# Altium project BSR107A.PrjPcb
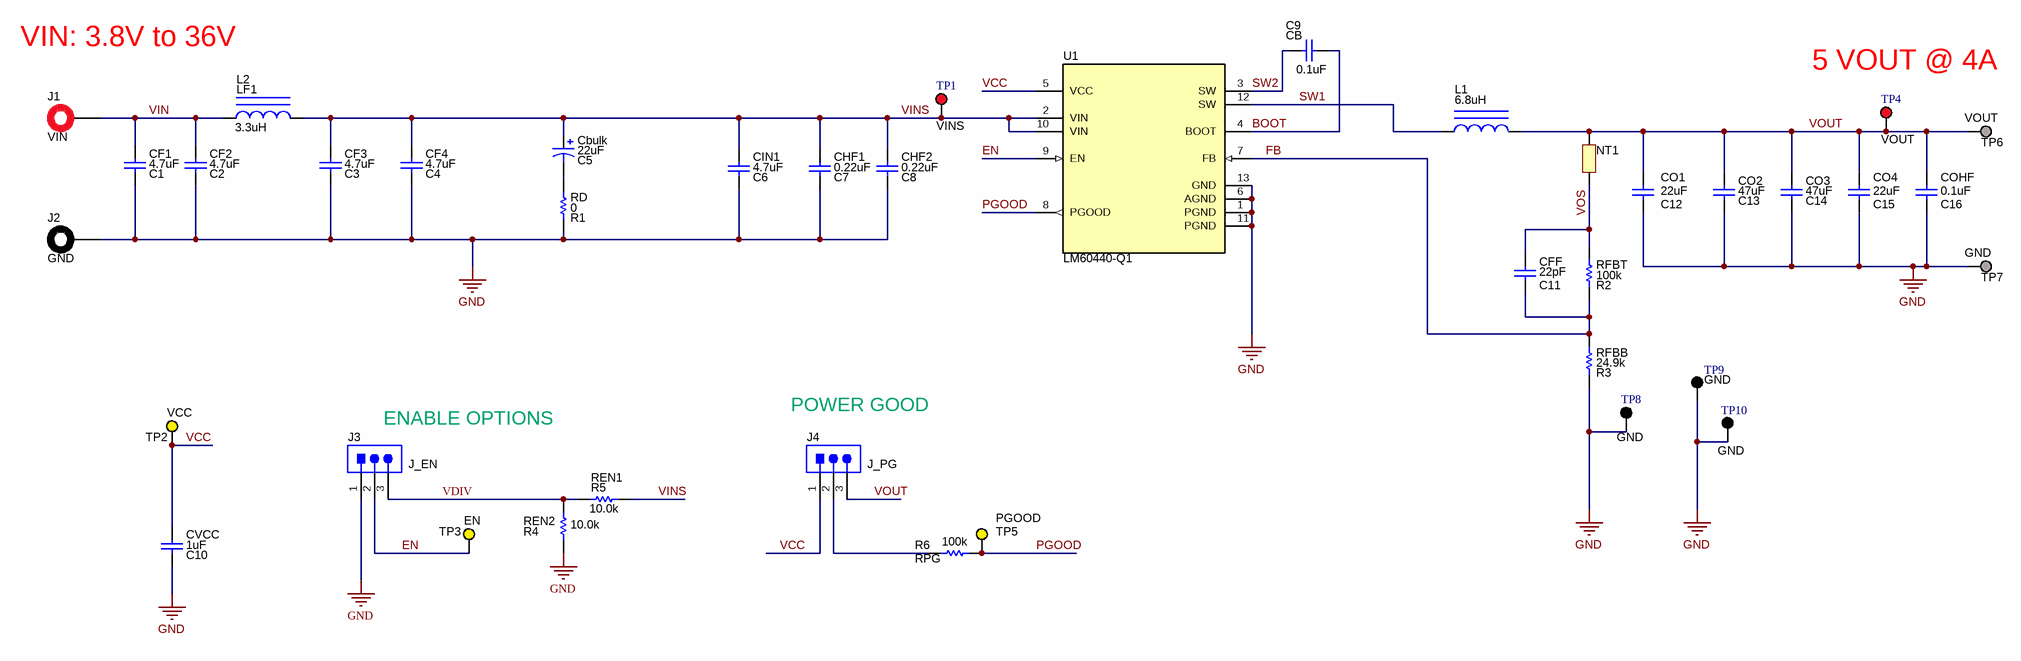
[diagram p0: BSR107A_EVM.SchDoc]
CopyrightYear: 2019; EVM_orderable: LM60440AQEVM; PCB_Layout: Ethan; PCB_Rev: A; PRJ_Customer: Public Release; PRJ_Engineer: Ethan Than; PRJ_Number: BSR107; PRJ_Title: LM60440AQEVM; SCH_Rev: A; TechSupport: http://www.ti.com/support; TID: N/A
2 sheets, 59 parts. Net scope: global (net labels, ports and power ports of the same name join across sheets).
Board file: BSR107A_PCB.PcbDoc
Sheets:
  BSR107A_EVM.SchDoc
  BSR107A_EVM_Hardware.SchDoc

## Sheet BSR107A_EVM.SchDoc
size 431 x 279 mm; Date: Not shown in title block; ApprovedBy: Not shown in title block; CheckedBy: Not shown in title block; Author: Not shown in title block; CompanyName: Not shown in title block; Engineer: Not shown in title block; Organization: Not shown in title block; Address1: Not shown in title block; Address2: Not shown in title block; Address3: Not shown in title block; Address4: Not shown in title block; DocumentNumber: 1; Revision: Use project parameter SCH_Rev; SheetNumber: 1; SheetTotal: 2; PageSetup: Record=PageOptions¦CenterHorizontal=True¦CenterVertical=True¦PrintScale=1.00¦XCorrection=1.00¦YCorrection=1.00¦PrintKind=0¦BorderSize=5000000¦LeftOffset=0¦BottomOffset=0¦Orientation=2¦PaperLength=1000¦PaperWidth=1000¦Scale=100¦PaperSource=15¦PrintQuality=600¦MediaType=1¦DitherType=10¦PaperKind=Letter¦PrintScaleMode=1

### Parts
C1  CF1  ValueDisplayed: 4.7uF  [1206_180]
C2  CF2  ValueDisplayed: 4.7uF  [1206_180]
C3  CF3  ValueDisplayed: 4.7uF  [1206_180]
C4  CF4  ValueDisplayed: 4.7uF  [1206_180]
C5  Cbulk  ValueDisplayed: 22uF  [SM_RADIAL_D]
C6  CIN1  ValueDisplayed: 4.7uF  [0805L]
C7  CHF1  ValueDisplayed: 0.22uF  [0603L]
C8  CHF2  ValueDisplayed: 0.22uF  [0603L]
C9  CB  ValueDisplayed: 0.1uF  [0603L]
C10  CVCC  ValueDisplayed: 1uF  [0603L]
C11  CFF  ValueDisplayed: 22pF  [0603L]
C12  CO1  ValueDisplayed: 22uF  [1210L]
C13  CO2  ValueDisplayed: 47uF  [1210_270L]
C14  CO3  ValueDisplayed: 47uF  [1210_270L]
C15  CO4  ValueDisplayed: 22uF  [1210L]
C16  COHF  ValueDisplayed: 0.1uF  [0603L]
J1  VIN  [6091]
J2  GND  [6092]
J3  J_EN  [Samtec_HTSW-103-07-G-S]
J4  J_PG  [Samtec_HTSW-103-07-G-S]
L1  ValueDisplayed: 6.8uH  [XAL6060]  (hidden comment: XAL6060-682MEB)
L2  LF1  ValueDisplayed: 3.3uH  [XAL4030]
NT1  Net-Tie  [Net-Tie_10mil]  (value not drawn)  (net tie, no BOM)
R1  RD  ValueDisplayed: 0  [0603]
R2  RFBT  ValueDisplayed: 100k  [0603L]
R3  RFBB  ValueDisplayed: 24.9k  [0603L]
R4  REN2  ValueDisplayed: 10.0k  [0603L]
R5  REN1  ValueDisplayed: 10.0k  [0603L]
R6  RPG  ValueDisplayed: 100k  [0603L]
TP1  VINS  [Keystone5010]
TP2  VCC  [Keystone5014]
TP3  EN  [Keystone5014]
TP4  VOUT  [Keystone5010]
TP5  PGOOD  [Keystone5014]
TP6  VOUT  [Keystone1503-2]
TP7  GND  [Keystone1503-2]
TP8  GND  [Keystone5011]
TP9  GND  [Keystone5011]
TP10  GND  [Keystone5011]
U1  LM60440-Q1  [RPK0013A]

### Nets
GND: C1.2 C2.2 C3.2 C4.2 C6.2 C7.2 C8.2 C10.2 C12.2 C13.2 C14.2 C15.2 C16.2 J2.1 J3.1 R1.1 R3.1 R4.1 TP7.1 TP8.1 TP9.1 TP10.1 U1.1(PGND) U1.6(AGND) U1.11(PGND) U1.13(GND)
BOOT: C9.2 U1.4(BOOT)
EN: J3.2 TP3.1 U1.9(EN)
FB: C11.2 R2.1 R3.2 U1.7(FB)
PGOOD: R6.2 TP5.1 U1.8(PGOOD)
SW1: L1.1 U1.12(SW)
SW2: C9.1 U1.3(SW)
VCC: C10.1 J4.1 TP2.1 U1.5(VCC)
VDIV: J3.3 R4.2 R5.1
VIN: C1.1 C2.1 J1.1 L2.1
VINS: C3.1 C4.1 C5.1(+) C6.1 C7.1 C8.1 L2.2 R5.2 TP1.1 U1.2(VIN) U1.10(VIN)
VOS: C11.1 NT1.1 R2.2
VOUT: C12.1 C13.1 C14.1 C15.1 C16.1 J4.3 L1.2 NT1.2 TP4.1 TP6.1
NetC5_2: C5.2(-) R1.2
NetJ4_2: J4.2 R6.1

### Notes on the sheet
- VIN: 3.8V to 36V
- 5 VOUT @ 4A
- (near J3) ENABLE OPTIONS
- POWER GOOD

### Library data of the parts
C1-C4 = CMP-0008969-2: CAP, CERM, 4.7 uF, 50 V, +/- 10%, X7R, 1206; Manufacturer: MuRata; PartNumber: GRM31CR71H475KA12L; TaMin_C: -55°C; Polarized: N; SizeAreaWB_mm2: 10.92; Value1: Unknown; U/M: EA; Value: 4.7uF; TaMax_C: 125°C; SizeZ_mm: 1.8; SizeX_mm: 3.2; SizeY_mm: 1.6; Cap_Case: 2220; Value2: 50V; SizeArea_mm2: 5.12; Cap_F: 4.7µF; AEC Category: Q200
C5 = CMP-0011179-2: CAP, AL, 22 uF, 50 V, +/- 20%, 0.88 ohm, AEC-Q200 Grade 2, SMD; Manufacturer: Panasonic; PartNumber: EEE-FK1H220P; TaMin_C: -55°C; ESR_ohm: 0.88; Polarized: Y; SizeAreaWB_mm2: 84.28; U/M: EA; Value: 22uF; TaMax_C: 105°C; SizeZ_mm: 5.4; SizeX_mm: 7.8; SizeY_mm: 6.6; Cap_Case: D; Value2: 50V; SizeArea_mm2: 51.48; CompType: Capacitor; Cap_F: 22µF; IRMS_A: 165mA; AEC Grade: 2; AEC Category: Q200
C6 = CMP-0007840-2: CAP, CERM, 4.7 uF, 50 V, +/- 10%, X5R, 0805; Manufacturer: TDK; PartNumber: C2012X5R1H475K125AB; TaMin_C: -55°C; ESR_ohm: 2.346m; Polarized: N; SizeAreaWB_mm2: 6.75; Value1: 0.002346 ohm; U/M: EA; Value: 4.7uF; TaMax_C: 85°C; SizeZ_mm: 1.45; SizeX_mm: 2; SizeY_mm: 1.25; Cap_Case: 0805; Value2: 50V; SizeArea_mm2: 2.5; CompType: Capacitor; Cap_F: 4.7µF; IRMS_A: 4.26021A; AEC Category: Q200
C7 C8 = CMP-0007047-4: CAP, CERM, 0.22 uF, 50 V, +/- 10%, X7R, 0603; Manufacturer: TDK; PartNumber: C1608X7R1H224K080AB; TaMin_C: -55°C; ESR_ohm: 0.021699; Polarized: N; SizeAreaWB_mm2: 4.68; Value1: 0.021699 ohm; U/M: EA; Value: 0.22uF; TaMax_C: 125°C; SizeZ_mm: 1; SizeX_mm: 1.6; SizeY_mm: 0.8; Cap_Case: 0603; Value2: 50V; SizeArea_mm2: 1.28; CompType: Capacitor; Cap_F: 220nF; IRMS_A: 1.12496A; AEC Category: Q200
C9 C16 = CMP-0006753-4: CAP, CERM, 0.1 uF, 25 V, +/- 10%, X7R, 0603; Manufacturer: AVX; PartNumber: 06033C104KAT2A; TaMin_C: -55°C; ESR_ohm: 0.05; Polarized: N; SizeAreaWB_mm2: 4.68; Value1: 0.05 ohm; U/M: EA; Value: 0.1uF; TaMax_C: 125°C; SizeZ_mm: 1; SizeX_mm: 1.6; SizeY_mm: 0.8; Cap_Case: 0603; Value2: 25V; SizeArea_mm2: 1.28; CompType: Capacitor; Cap_F: 100nF; AEC Category: Q200
C10 = CMP-0006833-4: CAP, CERM, 1 uF, 25 V, +/- 10%, X7R, 0603; Manufacturer: Wurth Elektronik; PartNumber: 885012206076; TaMin_C: -55°C; Polarized: N; SizeAreaWB_mm2: 4.68; Value1: Unknown; U/M: EA; Value: 1uF; TaMax_C: 125°C; SizeZ_mm: 1; SizeX_mm: 1.6; SizeY_mm: 0.8; Cap_Case: 0603; Value2: 25V; SizeArea_mm2: 1.28; CompType: Capacitor; Cap_F: 1µF; AEC Category: Q200
C11 = CMP-0007196-2: CAP, CERM, 22 pF, 50 V, +/- 5%, C0G/NP0, 0603; Manufacturer: MuRata; PartNumber: GRM1885C1H220JA01D; TaMin_C: -55°C; Polarized: N; SizeAreaWB_mm2: 4.68; Value1: Unknown; U/M: EA; Value: 22pF; TaMax_C: 125°C; SizeZ_mm: 1; SizeX_mm: 1.6; SizeY_mm: 0.8; Cap_Case: 0603; Value2: 50V; SizeArea_mm2: 1.28; AEC Category: Q200
C12 C15 = CMP-0009169-2: CAP, CERM, 22 uF, 25 V, +/- 10%, X5R, 1210; Manufacturer: Samsung Electro-Mechanics; PartNumber: CL32A226KAJNNNE; TaMin_C: -55°C; Polarized: N; SizeAreaWB_mm2: 14.7; Value1: Unknown; U/M: EA; Value: 22uF; TaMax_C: 85°C; SizeZ_mm: 1.35; SizeX_mm: 3.2; SizeY_mm: 2.5; Cap_Case: 1210; Value2: 25V; SizeArea_mm2: 8; CompType: Capacitor; Cap_F: 22µF; AEC Category: Q200
C13 C14 = CMP-0009211-2: CAP, CERM, 47 uF, 16 V, +/- 10%, X5R, 1210; Manufacturer: MuRata; PartNumber: GRM32ER61C476KE15L; TaMin_C: -55°C; Polarized: N; SizeAreaWB_mm2: 14.7; Value1: Unknown; U/M: EA; Value: 47uF; TaMax_C: 85°C; SizeZ_mm: 2.7; SizeX_mm: 3.2; SizeY_mm: 2.5; Cap_Case: 1210; Value2: 16V; SizeArea_mm2: 8; Cap_F: 47µF; AEC Category: Q200
J1 = CMP-0055167-2: Standard Banana Jack, Insulated, Red; Manufacturer: Keystone; CT: TRUE; Green_REACh: Passed; CNHeader: FALSE; Green_Lifecycle: Active
J2 = CMP-0055168-2: Standard Banana Jack, Insulated, Black; Manufacturer: Keystone; CT: TRUE; Green_REACh: Passed; CNHeader: FALSE; Green_Lifecycle: Active
J3 J4 = CMP-0075484-1: Header, 100mil, 3x1, Gold, TH; PartNumber: HTSW-103-07-G-S; Manufacturer: Samtec; CNHeader: True; CT: False; Green_Lifecycle: Active; Green_REACh: Passed
L1 = CMP-0061022-2: Inductor, Shielded, Composite, 6.8 µH, 9 A, 0.0208 ohm, AEC-Q200 Grade 1, SMD; Manufacturer: Coilcraft; Irms: 9.6A @ 40C rise; DCR_ohm: 0.0208; SizeAreaWB_mm2: 71.5616; AEC Grade: 1; Ind_H: 6.8µH; SizeArea_mm2: 41.7216; Value2: 9.2A; Green_REACh: Incomplete; SizeX_mm: 6.36; SizeZ_mm: 6.1; Value: 6.8uH; AEC Qualified: Y; Green_Lifecycle: Not Set; SizeY_mm: 6.56; Isat: 9.2A @ 30% inductance drop; AEC Category: Q200
L2 = CMP-0060989-1: Inductor, Shielded, Composite, 3.3 uH, 5.5 A, 0.026 ohm, SMD; Manufacturer: Coilcraft; PartNumber: XAL4030-332MEB; Isat: 5.5A @ 30% inductance drop; Irms: 6.6A @ 40C rise; Green_Lifecycle: Not Set; SizeAreaWB_mm2: 25; DCR_ohm: 0.026; Green_REACh: Incomplete; Value: 3.3uH; Imax_A: 5.5A; SizeZ_mm: 3.1; SizeX_mm: 4; SizeArea_mm2: 16; Ind_H: 3.3µH; AEC Category: Q200
NT1 = CMP-0078142-2: Single point connection between nets.
R1 = CMP-0023343-3: RES, 0, 1%, 0.1 W, AEC-Q200 Grade 0, 0603; PartNumber: RMCF0603ZT0R00; Manufacturer: Stackpole Electronics Inc; Value: 0; Power_W: 100mW; Value2: 0.1W; TempCo: ppm/C; SizeArea_mm2: 1.28; SizeX_mm: 1.6; SizeY_mm: 0.8; SizeZ_mm: 1; AEC Category: Q200; AEC Qualified: Y; U/M: EA
R2 = CMP-0022735-5: RES, 100 k, 1%, 0.1 W, 0603; Manufacturer: Yageo; PartNumber: RC0603FR-07100KL; Power_W: 100mW; TempCo: 100 ppm/C; Value: 100k; EIA_Code: E96; SizeX_mm: 1.6; SizeY_mm: 0.8; SizeZ_mm: 1; Value2: 0.1W; SizeArea_mm2: 1.28; CompType: Resistor; AEC Qualified: N; VDC_V: 75V; AEC Category: Q200; SizeAreaWB_mm2: 4.68
R3 = CMP-0022237-4: RES, 24.9 k, 1%, 0.1 W, AEC-Q200 Grade 0, 0603; Manufacturer: Vishay-Dale; PartNumber: CRCW060324K9FKEA; Power_W: 100mW; TempCo: 100 ppm/C; Value_Code: 24k9; Value: 24.9k; EIA_Code: E96; SizeX_mm: 1.6; SizeY_mm: 0.8; SizeZ_mm: 1; Value2: 0.1W; SizeArea_mm2: 1.28; CompType: Resistor; AEC Qualified: Y; VDC_V: 75V; AEC Category: Q200; AEC Grade: 0
R4 R5 = CMP-0021998-4: RES, 10.0 k, 1%, 0.1 W, AEC-Q200 Grade 0, 0603; PartNumber: CRCW060310K0FKEA; Manufacturer: Vishay-Dale; CompType: Resistor; Value: 10.0k; Res_ohm: 10k; Value_Code: 10k0; Power_W: 100mW; Value2: 0.1W; VDC_V: 75V; TempCo: 100 ppm/C; SizeArea_mm2: 1.28; SizeX_mm: 1.6; SizeY_mm: 0.8; SizeZ_mm: 1; EIA_Code: E96; AEC Category: Q200; AEC Qualified: Y; AEC Grade: 0
R6 = CMP-0021990-4: RES, 100 k, 1%, 0.1 W, AEC-Q200 Grade 0, 0603; PartNumber: CRCW0603100KFKEA; Manufacturer: Vishay-Dale; CompType: Resistor; Value: 100k; Power_W: 100mW; Value2: 0.1W; VDC_V: 75V; TempCo: 100 ppm/C; EIA_Code: E96; SizeArea_mm2: 1.28; SizeX_mm: 1.6; SizeY_mm: 0.8; SizeZ_mm: 1; AEC Category: Q200; AEC Qualified: Y; AEC Grade: 0
TP1 TP4 = CMP-0055147-1: Test Point, Multipurpose, Red, TH; Manufacturer: Keystone; ContactFinish: Silver; Green_Lifecycle: Active; Green_REACh: Passed; CNHeader: FALSE; CT: TRUE
TP2 TP3 TP5 = CMP-0055151-1: Test Point, Multipurpose, Yellow, TH; Manufacturer: Keystone; PartNumber: 5014; ContactFinish: Silver; CNHeader: FALSE; CT: TRUE; Green_Lifecycle: Active; Green_REACh: Passed
TP6 TP7 = 1503-2: Terminal, Turret, TH, Double; Manufacturer: Keystone; CompType: Turret Terminal; Green_Lifecycle: Active; Green_REACh: Passed
TP8-TP10 = CMP-0055148-1: Test Point, Multipurpose, Black, TH; Manufacturer: Keystone; CNHeader: FALSE; Green_Lifecycle: Active; Green_REACh: Passed; ContactFinish: Silver; CT: TRUE
U1 = CMP-0085873-1: LM60440-Q1, RPK0013A (VQFN-12); Alternate PartNumber: LM60440AQRPKRQ1; Manufacturer: Texas Instruments; SizeAreaWB_mm2: 12; SizeY_mm: 3; CompType: IC; SizeX_mm: 2; SizeZ_mm: 0.7; AEC Category: Q200; AEC Qualified: N; SizeArea_mm2: 6

## Sheet BSR107A_EVM_Hardware.SchDoc
size 431 x 279 mm; Date: Not shown in title block; ApprovedBy: Not shown in title block; CheckedBy: Not shown in title block; Author: Not shown in title block; CompanyName: Not shown in title block; Engineer: Not shown in title block; Organization: Not shown in title block; Address1: Not shown in title block; Address2: Not shown in title block; Address3: Not shown in title block; Address4: Not shown in title block; DocumentNumber: 2; Revision: Use project parameter SCH_Rev; SheetNumber: 2; SheetTotal: 2; PageSetup: Record=PageOptions¦CenterHorizontal=True¦CenterVertical=True¦PrintScale=1.00¦XCorrection=1.00¦YCorrection=1.00¦PrintKind=0¦BorderSize=5000000¦LeftOffset=0¦BottomOffset=0¦Orientation=2¦PaperLength=1000¦PaperWidth=1000¦Scale=100¦PaperSource=15¦PrintQuality=600¦MediaType=1¦DitherType=10¦PaperKind=Letter¦PrintScaleMode=1
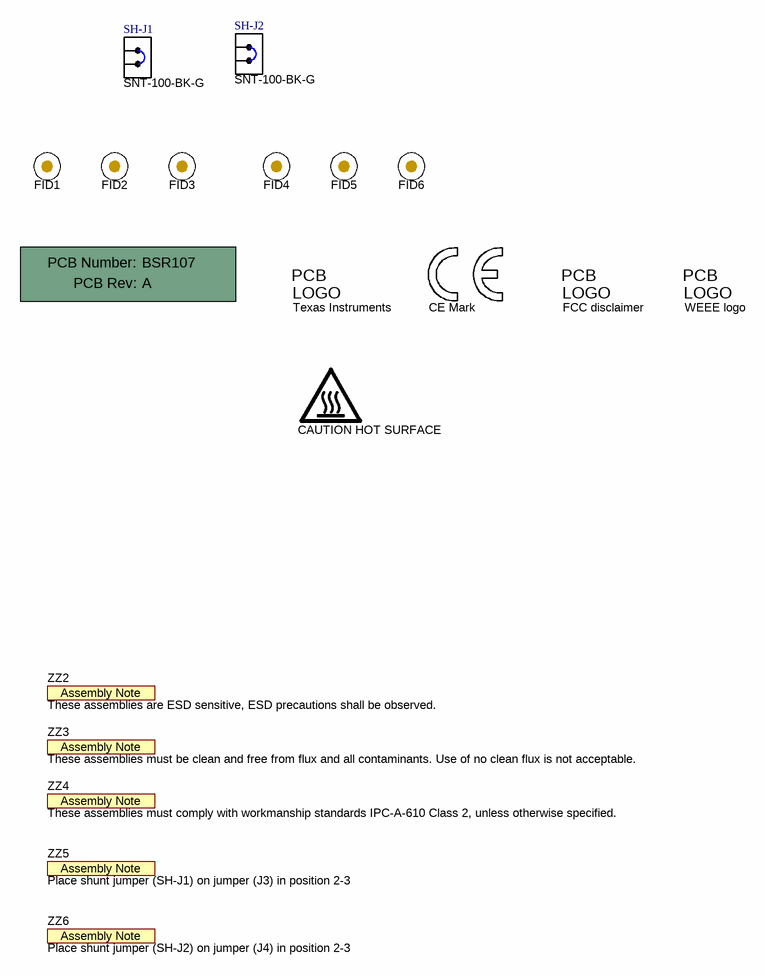
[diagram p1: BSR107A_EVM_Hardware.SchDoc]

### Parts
!PCB1  Printed Circuit Board  (value not drawn)  (mechanical)
FID1  Fiducial  [Fiducial10-20]  (value not drawn)
FID2  Fiducial  [Fiducial10-20]  (value not drawn)
FID3  Fiducial  [Fiducial10-20]  (value not drawn)
FID4  Fiducial  [Fiducial10-20]  (value not drawn)
FID5  Fiducial  [Fiducial10-20]  (value not drawn)
FID6  Fiducial  [Fiducial10-20]  (value not drawn)
Logo1  Texas Instruments  [TI_Stacked_Overlay_Small]  (no BOM)
Logo2  CE Mark  [CE_Mark_5mm]  (no BOM)
Logo3  FCC disclaimer  [FCC_disclaimer]  (no BOM)
Logo4  WEEE logo  [WEEE_Minimum]  (no BOM)
LOGO5  CAUTION HOT SURFACE  [IEC_HotSurface_Small]  (no BOM)
SH-J1  SNT-100-BK-G  [SNT-100-BK-G]
SH-J2  SNT-100-BK-G  [SNT-100-BK-G]
ZZ2  These assemblies are ESD sensitive, ESD precautions shall be observed.  [AssemblyNote]  (no BOM)
ZZ3  These assemblies must be clean and free from flux and all contaminants. Use of no clean flux is not acceptable.  [AssemblyNote]  (no BOM)
ZZ4  These assemblies must comply with workmanship standards IPC-A-610 Class 2, unless otherwise specified.  [AssemblyNote]  (no BOM)
ZZ5  Place shunt jumper (SH-J1) on jumper (J3) in position 2-3  [AssemblyNote]  (no BOM)
ZZ6  Place shunt jumper (SH-J2) on jumper (J4) in position 2-3  [AssemblyNote]  (no BOM)

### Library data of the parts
!PCB1 = CMP-0003618-2: Manufacturer: Any; PartNumber: BSR107
FID1-FID6 = CMP-0077181-1: Fiducial mark.  There is nothing to buy or mount.
Logo1 = CMP-0074838-1: Texas Instrument Corporate Signature; SymbolCreator: a0412235; Lib Reference: TI_Logo; Library Reference: Logo
Logo2 = CMP-0074844-1: SymbolCreator: a0412235
Logo3 = CMP-0074847-1: FCC_disclaimer; Library Reference: Logo
Logo4 = CMP-0074769-1
LOGO5 = CMP-0074837-1: IEC 61010-1 Hot Surface Warning; Library Reference: IEC_HotSurface; SymbolCreator: a0412235
SH-J1 SH-J2 = CMP-0003623-1: Shunt, 100mil, Gold plated, Black; Alternate PartNumber: 969102-0000-DA; Manufacturer: Samtec; Alternate Manufacturer: 3M; Value: 1x2; Note: You can "mate" this to a header by matching the designator.  i.e. use SH-J3 for header J3
ZZ2 = CMP-0077236-1
ZZ3 = CMP-0077237-1
ZZ4 = CMP-0077238-1
ZZ5 ZZ6 = CMP-0077238-1: These assemblies must comply with workmanship standards IPC-A-610 Class 2, unless otherwise specified.

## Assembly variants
001: not fitted C3 C4 C11 C15 FID1 FID2 FID3 FID4 FID5 FID6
